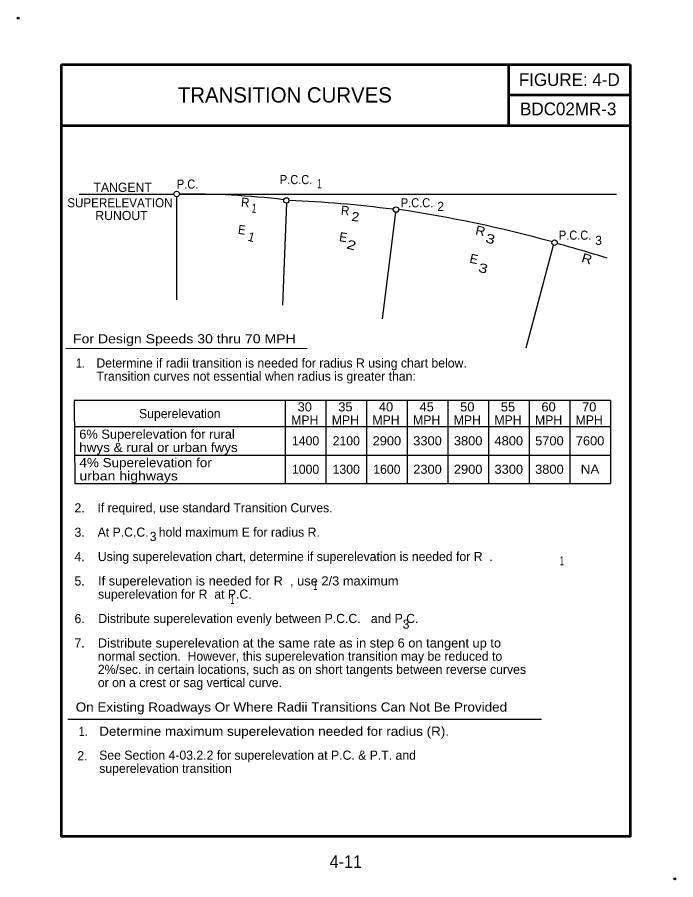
# Model space of a CAD drawing. Extents: x -2.54 to -1.7, y 1.64 to 2.75.
import ezdxf
from ezdxf.enums import TextEntityAlignment as Align

# ---------------------------------------------------------------- set-up
doc = ezdxf.new("R2010")
doc.units = 0
doc.header["$LTSCALE"] = 0.0047
doc.header["$PDMODE"] = 32
doc.header["$PDSIZE"] = 0.00235
doc.layers.add('1', color=7, linetype='Continuous', lineweight=25)

msp = doc.modelspace()

# ---------------------------------------------------------------- linework, layer by layer
at = {"layer": '1', "lineweight": 53}
for p, q in [((-1.914146, 2.688937), (-1.914146, 2.610812)), ((-1.914146, 2.649875), (-1.757896, 2.649875)), ((-2.487062, 2.610812), (-1.757896, 2.610812))]:
    msp.add_line(p, q, dxfattribs=at)
at = {"layer": '1'}
for p, q in [((-2.464313, 2.522781), (-2.342823, 2.522781)), ((-2.335812, 2.522781), (-1.775719, 2.522781)), ((-2.339313, 2.519271), (-2.339313, 2.387365)), ((-2.198635, 2.51101), (-2.203771, 2.380365)), ((-2.058812, 2.499344), (-2.075698, 2.362958)), ((-1.856635, 2.456802), (-1.891583, 2.325083)), ((-2.200031, 2.258115), (-2.200031, 2.151844)), ((-2.147948, 2.258115), (-2.147948, 2.151844)), ((-2.095865, 2.258115), (-2.095865, 2.151844)), ((-2.043781, 2.258115), (-2.043781, 2.151844)), ((-1.991698, 2.258115), (-1.991698, 2.151844)), ((-1.939615, 2.258115), (-1.939615, 2.151844)), ((-1.887531, 2.258115), (-1.887531, 2.151844)), ((-1.835448, 2.258115), (-1.835448, 2.151844)), ((-1.783365, 2.258115), (-1.783365, 2.151844)), ((-2.470458, 2.22476), (-1.783365, 2.22476)), ((-2.470177, 2.188302), (-1.783365, 2.188302)), ((-2.469885, 2.151844), (-1.783365, 2.151844)), ((-2.478771, 1.849948), (-1.871646, 1.849948))]:
    msp.add_line(p, q, dxfattribs=at)
at = {"layer": '1', "lineweight": 13}
msp.add_line((-2.48151, 2.324896), (-2.172115, 2.324896), dxfattribs=at)
at = {"layer": '1', "lineweight": 53}
for points in [[(-1.757896, 2.688937), (-1.757896, 1.699354), (-2.487062, 1.699354), (-2.487062, 2.688937)], [(-2.487062, 2.688937), (-1.914146, 2.688937), (-1.757896, 2.688937)]]:
    msp.add_lwpolyline(points, dxfattribs=at)
at = {"layer": '1'}
msp.add_lwpolyline([(-1.783365, 2.258115), (-2.470719, 2.258115), (-2.469885, 2.151844)], dxfattribs=at)
for centre in [(-2.339315, 2.522776), (-2.198612, 2.514612), (-2.058195, 2.502958), (-1.854862, 2.460406)]:
    msp.add_circle(centre, 0.003497, dxfattribs=at)
for centre, radius, start, end in [((-2.326016, 1.463307), 1.059514, 83.27729, 90.52979), ((-2.261058, 0.957705), 1.558303, 82.67679, 87.57446), ((-2.301053, 0.842078), 1.679052, 74.73835, 81.56276), ((-2.29071, 0.838667), 1.679052, 72.56311, 74.83588)]:
    msp.add_arc(centre, radius, start, end, dxfattribs=at)
for p in [(-2.542417, 2.748219), (-1.70075, 1.645094)]:
    msp.add_point(p, dxfattribs=at)

# ---------------------------------------------------------------- texts
for s, height, p in [('FIGURE: 4-D', 0.01628, (-1.836021, 2.66126)), ('TRANSITION CURVES', 0.01953, (-2.200604, 2.640104)), ('BDC02MR-3', 0.01628, (-1.837401, 2.623802)), ('TANGENT', 0.01172, (-2.408526, 2.525573)), ('2', 0.01172, (-2.000906, 2.501094)), ('RUNOUT', 0.01172, (-2.409979, 2.489437)), ('3', 0.01172, (-1.798552, 2.457542)), ('Superelevation', 0.01172, (-2.33525, 2.235573)), ('MPH', 0.01172, (-2.175073, 2.22726)), ('MPH', 0.01172, (-2.12299, 2.22726)), ('MPH', 0.01172, (-2.070906, 2.22726)), ('MPH', 0.01172, (-2.018823, 2.22726)), ('MPH', 0.01172, (-1.96674, 2.22726)), ('MPH', 0.01172, (-1.914656, 2.22726)), ('MPH', 0.01172, (-1.862573, 2.22726)), ('MPH', 0.01172, (-1.81049, 2.22726)), ('1400', 0.01172, (-2.173995, 2.200667)), ('2100', 0.01172, (-2.121911, 2.200667)), ('1000', 0.01172, (-2.173995, 2.164208)), ('1300', 0.01172, (-2.121911, 2.164208)), ('1600', 0.01172, (-2.069828, 2.164208)), ('3', 0.01172, (-2.369427, 2.078052)), ('3', 0.01172, (-2.04525, 1.965677))]:
    msp.add_text(s, height=height, dxfattribs=at).set_placement(p, align=Align.CENTER)
for s, height, width, p in [('P.C.C.', 0.01172, 0.9, (-2.186182, 2.535479)), ('P.C.', 0.01172, 0.9, (-2.325307, 2.529667)), ('1', 0.01172, 0.6, (-2.156125, 2.53024)), ('SUPERELEVATION', 0.01172, 0.95, (-2.412047, 2.50576)), ('P.C.C.', 0.01172, 0.9, (-2.031193, 2.50576)), ('P.C.C.', 0.01172, 0.9, (-1.828578, 2.464229)), ('30', 0.01172, 1.05, (-2.175078, 2.244187)), ('35', 0.01172, 1.05, (-2.12299, 2.244187)), ('40', 0.01172, 1.05, (-2.070911, 2.244187)), ('45', 0.01172, 1.05, (-2.018823, 2.244187)), ('50', 0.01172, 1.05, (-1.966745, 2.244187)), ('55', 0.01172, 1.05, (-1.914656, 2.244187)), ('60', 0.01172, 1.05, (-1.862578, 2.244187)), ('70', 0.01172, 1.05, (-1.810495, 2.244187)), ('2900', 0.01172, 1.05, (-2.069823, 2.200667)), ('3300', 0.01172, 1.05, (-2.01774, 2.200667)), ('3800', 0.01172, 1.05, (-1.965656, 2.200667)), ('4800', 0.01172, 1.05, (-1.913573, 2.200667)), ('5700', 0.01172, 1.05, (-1.86149, 2.200667)), ('7600', 0.01172, 1.05, (-1.809406, 2.200667)), ('2300', 0.01172, 1.05, (-2.01774, 2.164208)), ('2900', 0.01172, 1.05, (-1.965656, 2.164208)), ('3300', 0.01172, 1.05, (-1.913573, 2.164208)), ('3800', 0.01172, 1.05, (-1.86149, 2.164208)), ('NA', 0.01172, 1.1, (-1.809411, 2.164208)), ('1', 0.01172, 0.6, (-1.845427, 2.046844)), ('1', 0.01172, 0.6, (-2.16151, 2.015437)), ('1', 0.01172, 0.6, (-2.267802, 1.99751)), ('4-11', 0.01628, 0.95, (-2.122479, 1.658979))]:
    msp.add_text(s, height=height, dxfattribs=dict(at, width=width)).set_placement(p, align=Align.CENTER)
for s, rotation, width, p in [('R', 356.036, 0.95, (-2.251733, 2.506184)), ('1', 354.997, 0.7, (-2.240485, 2.498782)), ('R', 354.976, 0.95, (-2.123711, 2.495877)), ('2', 354.453, 1.15, (-2.110728, 2.487969)), ('E', 352.668, 0.9, (-2.25644, 2.471224)), ('R', 347.964, 1.1, (-1.951045, 2.469931)), ('1', 345.144, 0.95, (-2.244903, 2.462126)), ('E', 351.293, 0.95, (-2.126658, 2.461716)), ('3', 345.301, 1.35, (-1.938617, 2.459724)), ('2', 344.696, 1.35, (-2.116734, 2.451805)), ('R', 343.515, 1.15, (-1.815017, 2.434328)), ('3', 345.598, 1.35, (-1.947895, 2.422034))]:
    msp.add_text(s, height=0.01172, rotation=rotation, dxfattribs=dict(at, width=width)).set_placement(p, align=Align.CENTER)
msp.add_text('E', height=0.01172, rotation=347.378, dxfattribs=at).set_placement((-1.959463, 2.433916), align=Align.CENTER)
for s, width, p in [('For Design Speeds 30 thru 70 MPH', 1.15, (-2.472177, 2.331437)), ('6% Superelevation for rural', 1.05, (-2.464156, 2.209135)), ('hwys & rural or urban fwys', 1.1, (-2.464156, 2.192208)), ('4% Superelevation for', 1.1, (-2.463875, 2.172677)), ('urban highways', 1.15, (-2.463875, 2.15575)), ('If superelevation is needed for R  , use 2/3 maximum', 1.05, (-2.440052, 2.021104)), ('Distribute superelevation at the same rate as in step 6 on tangent up to', 1.05, (-2.440302, 1.941562)), ('On Existing Roadways Or Where Radii Transitions Can Not Be Provided', 1.1, (-2.468625, 1.859417)), ('Determine maximum superelevation needed for radius (R).', 1.1, (-2.438552, 1.828396))]:
    msp.add_text(s, height=0.01172, dxfattribs=dict(at, width=width)).set_placement(p)
at = {"layer": '1', "width": 0.85}
for p in [(-2.457135, 2.300302), (-2.453573, 1.828281)]:
    msp.add_text('1.', height=0.01172, dxfattribs=at).set_placement(p, align=Align.RIGHT)
at = {"layer": '1'}
for s, p in [('Determine if radii transition is needed for radius R using chart below.', (-2.442156, 2.300427)), ('Transition curves not essential when radius is greater than:', (-2.442156, 2.2835)), ('If required, use standard Transition Curves.', (-2.440792, 2.114854)), ('At P.C.C.   hold maximum E for radius R.', (-2.440542, 2.083604)), ('Using superelevation chart, determine if superelevation is needed for R  .', (-2.440302, 2.052354)), ('superelevation for R  at P.C.', (-2.440052, 2.004177)), ('Distribute superelevation evenly between P.C.C.   and P.C.', (-2.439677, 1.972927)), ('normal section.  However, this superelevation transition may be reduced to', (-2.440302, 1.924635)), ('2%/sec. in certain locations, such as on short tangents between reverse curves', (-2.440302, 1.907708)), ('or on a crest or sag vertical curve.', (-2.440302, 1.890781)), ('See Section 4-03.2.2 for superelevation at P.C. & P.T. and ', (-2.438552, 1.79774)), ('superelevation transition', (-2.438552, 1.780812))]:
    msp.add_text(s, height=0.01172, dxfattribs=at).set_placement(p)
for s, p in [('2.', (-2.457135, 2.114729)), ('3.', (-2.457135, 2.083479)), ('4.', (-2.457135, 2.052229)), ('5.', (-2.457135, 2.020979)), ('6.', (-2.457135, 1.972812)), ('7.', (-2.457135, 1.941562)), ('2.', (-2.453573, 1.797031))]:
    msp.add_text(s, height=0.01172, dxfattribs=at).set_placement(p, align=Align.RIGHT)

doc.saveas('drawing.dxf')
